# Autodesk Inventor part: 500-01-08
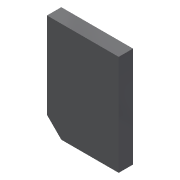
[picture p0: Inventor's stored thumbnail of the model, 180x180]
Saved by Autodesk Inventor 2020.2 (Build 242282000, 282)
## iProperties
Created: 2015-11
Part Number: 500-01-08
Material: Stal
Document SubType Name: Modeling
Designer: F.Stasiak
Density: 7.85 g/cm^3
Appearance: Stal
Description: Odbój
Manager: www.cadconsulting.pl
Company: Fabian Stasiak CAD Consulting
Author: F.Stasiak
Subject: Zbiór ćwiczeń. Autodesk Inventor 2020. Kurs podstawowy
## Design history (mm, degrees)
sketch "Szkic1"
  geometry: L1 (0, 0)-(50, 0); L2 (50, 0)-(50, 10); L3 (50, 10)-(0, 10); L4 (0, 10)-(0, 0)
  constraints: 8 end point, 2 parallel, 1 horizontal, 1 perpendicular
  dimensions: "d0" = 50 distance of L3.end L2.end; "d1" = 10 distance of L2.end L1.end
extrude "Wyciągnięcie proste1" new body sketch "Szkic1" distance "d2" = 70; taper "d3" = 0 deg
chamfer "Faza1" distance "d4" = 10; stored, may be unused: second distance "d5" = 2, angle "d6" = 45 deg
node "Bryła1"
